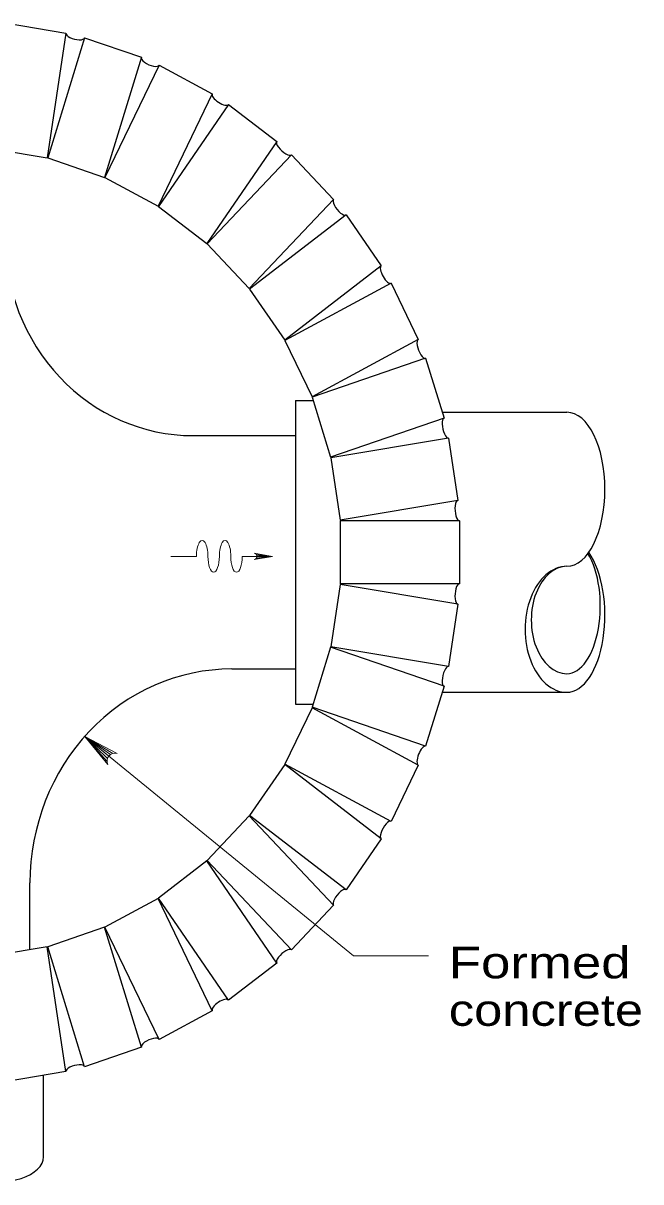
# Model space of a CAD drawing. Extents: x 1083.1 to 1117.1, y 697.4 to 741.4.
# Drawn here: x 1109.55 to 1112.61, y 723.02 to 728.75 of the extents above; entities that cross this region are included whole.
import ezdxf

# ---------------------------------------------------------------- set-up
doc = ezdxf.new("R2010")
doc.units = 0
doc.header["$LTSCALE"] = 0.062
doc.layers.add('1', color=7, linetype='Continuous', lineweight=13)

msp = doc.modelspace()

# ---------------------------------------------------------------- linework, layer by layer
at = {"layer": '1', "lineweight": 25}
for p, q in [((1109.47317, 728.75017), (1109.76417, 728.70133)), ((1109.76417, 728.70133), (1109.67192, 728.08517)), ((1109.8565, 728.67783), (1109.67442, 728.08458)), ((1109.8565, 728.67783), (1110.13675, 728.58142)), ((1110.13675, 728.58142), (1109.95467, 727.98817)), ((1110.2245, 728.543), (1109.957, 727.98708)), ((1110.2245, 728.543), (1110.48708, 728.40133)), ((1110.48708, 728.40133), (1110.2195, 727.8455)), ((1110.56808, 728.34883), (1110.22175, 727.84408)), ((1110.56808, 728.34883), (1110.80642, 728.16542)), ((1109.381, 728.134), (1109.67192, 728.08517)), ((1110.80642, 728.16542), (1110.46008, 727.66075)), ((1109.67442, 728.08458), (1109.95467, 727.98817)), ((1110.87867, 728.10008), (1110.462, 727.659)), ((1110.87867, 728.10008), (1111.087, 727.87958)), ((1109.957, 727.98708), (1110.2195, 727.8455)), ((1110.22175, 727.84408), (1110.46008, 727.66075)), ((1111.087, 727.87958), (1110.67033, 727.43842)), ((1111.14875, 727.80308), (1110.672, 727.43642)), ((1111.14875, 727.80308), (1111.32192, 727.55067)), ((1110.462, 727.659), (1110.67033, 727.43842)), ((1111.32192, 727.55067), (1110.84517, 727.184)), ((1111.3715, 727.46492), (1110.8465, 727.18175)), ((1111.3715, 727.46492), (1111.50525, 727.187)), ((1110.672, 727.43642), (1110.84517, 727.184)), ((1110.8465, 727.18175), (1110.98025, 726.90383)), ((1111.50525, 727.187), (1110.98025, 726.90383)), ((1111.54167, 727.09408), (1110.98125, 726.90125)), ((1111.54167, 727.09408), (1111.63267, 726.79742)), ((1110.89867, 726.88533), (1110.89875, 725.38517)), ((1110.89867, 726.88533), (1110.98617, 726.88533)), ((1110.89867, 726.88533), (1110.98617, 726.88533)), ((1110.98125, 726.90125), (1111.07233, 726.60467)), ((1111.62358, 726.82725), (1112.24, 726.82725)), ((1111.63267, 726.79742), (1111.07233, 726.60467)), ((1110.39142, 726.71192), (1110.89867, 726.71192)), ((1111.65492, 726.69958), (1111.07292, 726.602)), ((1111.65492, 726.69958), (1111.701, 726.3915)), ((1111.07292, 726.602), (1111.119, 726.29392)), ((1111.701, 726.3915), (1111.119, 726.29392)), ((1111.70842, 726.29125), (1111.11917, 726.29125)), ((1111.11917, 726.29125), (1111.11917, 725.97933)), ((1111.70842, 726.29125), (1111.70842, 725.97933)), ((1111.119, 725.97658), (1111.07292, 725.6685)), ((1111.701, 725.879), (1111.119, 725.97658)), ((1111.70842, 725.97933), (1111.11917, 725.97933)), ((1111.701, 725.879), (1111.65492, 725.57092)), ((1111.07233, 725.66592), (1110.98125, 725.36925)), ((1111.63267, 725.47308), (1111.07233, 725.66592)), ((1111.65492, 725.57092), (1111.07292, 725.6685)), ((1110.58475, 725.55858), (1110.89875, 725.55858)), ((1111.63267, 725.47308), (1111.54167, 725.17642)), ((1111.62358, 725.44325), (1112.24, 725.44325)), ((1110.89875, 725.38517), (1110.98617, 725.38517)), ((1110.98025, 725.36675), (1110.8465, 725.08883)), ((1111.50533, 725.0835), (1110.98025, 725.36675)), ((1111.54167, 725.17642), (1110.98125, 725.36925)), ((1110.84517, 725.0865), (1110.672, 724.83417)), ((1111.32192, 724.71983), (1110.84517, 725.0865)), ((1111.3715, 724.80558), (1110.8465, 725.08883)), ((1111.50533, 725.0835), (1111.3715, 724.80558)), ((1110.67033, 724.83208), (1110.462, 724.6115)), ((1111.087, 724.39092), (1110.67033, 724.83208)), ((1111.14875, 724.46742), (1110.672, 724.83417)), ((1111.32192, 724.71983), (1111.14875, 724.46742)), ((1110.46008, 724.60975), (1110.22175, 724.42642)), ((1110.80642, 724.10508), (1110.46008, 724.60975)), ((1110.87867, 724.17042), (1110.462, 724.6115)), ((1109.58617, 724.17092), (1109.58617, 724.50142)), ((1110.2195, 724.425), (1109.957, 724.28342)), ((1110.48708, 723.86917), (1110.2195, 724.425)), ((1110.56808, 723.92175), (1110.22175, 724.42642)), ((1111.087, 724.39092), (1110.87867, 724.17042)), ((1109.95467, 724.28233), (1109.67442, 724.18592)), ((1110.13675, 723.68908), (1109.95467, 724.28233)), ((1110.2245, 723.7275), (1109.957, 724.28342)), ((1109.672, 724.18533), (1109.381, 724.1365)), ((1109.76417, 723.56917), (1109.672, 724.18533)), ((1109.8565, 723.59267), (1109.67442, 724.18592)), ((1110.80642, 724.10508), (1110.56808, 723.92175)), ((1110.48708, 723.86917), (1110.2245, 723.7275)), ((1110.13675, 723.68908), (1109.8565, 723.59267)), ((1109.76417, 723.56917), (1109.47317, 723.52042)), ((1109.65392, 723.148), (1109.65392, 723.55067))]:
    msp.add_line(p, q, dxfattribs=at)
at = {"layer": '1'}
for p, q in [((1110.78567, 726.115), (1110.69508, 726.131)), ((1110.78567, 726.115), (1110.705, 726.12475)), ((1110.78567, 726.115), (1110.70517, 726.12467)), ((1110.40917, 726.115), (1110.28292, 726.115)), ((1110.78567, 726.115), (1110.63533, 726.115)), ((1110.78567, 726.115), (1110.69508, 726.09908)), ((1110.78567, 726.115), (1110.70475, 726.10508)), ((1110.78567, 726.115), (1110.70742, 726.11942)), ((1110.70758, 726.11117), (1110.78417, 726.11475)), ((1109.97567, 725.12842), (1109.85708, 725.22542)), ((1109.96875, 725.1155), (1109.85708, 725.22542)), ((1109.96692, 725.10358), (1109.85708, 725.22542)), ((1109.98408, 725.13617), (1109.85708, 725.22542)), ((1109.99533, 725.14133), (1109.85708, 725.22542))]:
    msp.add_line(p, q, dxfattribs=at)
for points in [[(1109.97175, 725.08592), (1109.85708, 725.22542), (1110.0165, 725.14075)], [(1109.85708, 725.22542), (1111.186, 724.14025), (1111.5565, 724.14025)]]:
    msp.add_lwpolyline(points, dxfattribs=at)
msp.add_arc((1110.00522, 725.10433), 0.0382, 72.81975, 208.64588, dxfattribs=at)
at = {"layer": '1', "lineweight": 25}
for centre, major_axis, ratio, start_param, end_param in [((1109.81034, 728.68959), (0.04614, -0.01196), 0.389747, 3.1535017, 6.2950944), ((1110.18064, 728.56221), (0.04376, -0.01956), 0.385427, 3.1598674, 6.3014601), ((1110.52755, 728.37507), (0.04029, -0.02663), 0.379662, 3.1641623, 6.3057549), ((1110.84255, 728.13278), (0.03584, -0.033), 0.373137, 3.166043, 6.3076357), ((1111.11786, 727.8413), (0.03053, -0.03852), 0.36655, 3.1654763, 6.307069), ((1110.39145, 727.69675), (0, 0.98483), 0.944544, 1.5707933, 3.1415918), ((1111.34672, 727.50781), (0.0245, -0.04308), 0.360529, 3.1626767, 6.3042693), ((1111.52348, 727.14053), (0.01791, -0.04658), 0.355583, 3.1580272, 6.2996199), ((1112.24003, 726.44665), (0, -0.3806), 0.493973, 6.2831853, 9.4247779), ((1111.64379, 726.74849), (0.01091, -0.04895), 0.352086, 3.1520106, 6.2936033), ((1111.7047, 726.34135), (0.00367, -0.05015), 0.350278, 3.1451597, 6.2867524), ((1112.24002, 725.86991), (0, -0.33452), 0.493973, 6.2831853, 8.7432884), ((1112.24003, 725.82385), (0, -0.3806), 0.493973, 6.2831853, 8.8122226), ((1112.24003, 725.75465), (0, -0.3114), 0.663452, 3.1415925, 6.2831852), ((1112.24003, 725.80072), (0, -0.26533), 0.663452, 3.1415925, 6.2831852), ((1111.7047, 725.92914), (-0.00366, -0.05015), 0.350278, 3.1380288, 6.2796215), ((1110.58476, 724.5014), (0, -1.05719), 0.944544, 3.1415885, 4.712393), ((1111.64379, 725.522), (-0.01091, -0.04895), 0.352085, 3.1311777, 6.2727704), ((1111.52347, 725.12997), (-0.01791, -0.04658), 0.355581, 3.1251606, 6.2667532), ((1111.34671, 724.76268), (-0.0245, -0.04308), 0.360527, 3.1205104, 6.2621031), ((1111.11785, 724.4292), (-0.03052, -0.03853), 0.366547, 3.1177098, 6.2593025), ((1110.84254, 724.13772), (-0.03583, -0.033), 0.373134, 3.117142, 6.2587347), ((1110.52755, 723.89543), (-0.04029, -0.02663), 0.37966, 3.1190216, 6.2606142), ((1110.18063, 723.70829), (-0.04376, -0.01956), 0.385425, 3.1233154, 6.2649081), ((1109.81034, 723.58091), (-0.04614, -0.01196), 0.389745, 3.1296802, 6.2712729), ((1109.4302, 723.14797), (-0.2237, 0), 0.553681, 0, 3.1415927)]:
    msp.add_ellipse(centre, major_axis=major_axis, ratio=ratio, start_param=start_param, end_param=end_param, dxfattribs=at)
at = {"layer": '1'}
for centre, major_axis, ratio, start_param, end_param in [((1110.43745, 726.11504), (0, -0.07867), 0.359358, 1.5707963, 4.712389), ((1110.55054, 726.11504), (0, -0.07867), 0.359358, 1.5707963, 4.712389), ((1110.69273, 726.11504), (0, -0.01618), 0.944544, 0.1533668, 2.9873365), ((1110.49399, 726.11504), (0, -0.07867), 0.359358, 4.712389, 7.8539816), ((1110.60708, 726.11504), (0, -0.07867), 0.359358, 4.712389, 7.8539816)]:
    msp.add_ellipse(centre, major_axis=major_axis, ratio=ratio, start_param=start_param, end_param=end_param, dxfattribs=at)

# ---------------------------------------------------------------- texts
for s, width, p in [('Formed', 1.25, (1111.65642, 724.02967)), ('concrete', 1.2, (1111.65642, 723.795))]:
    msp.add_text(s, height=0.156, dxfattribs=dict(at, width=width)).set_placement(p)

doc.saveas('drawing.dxf')
